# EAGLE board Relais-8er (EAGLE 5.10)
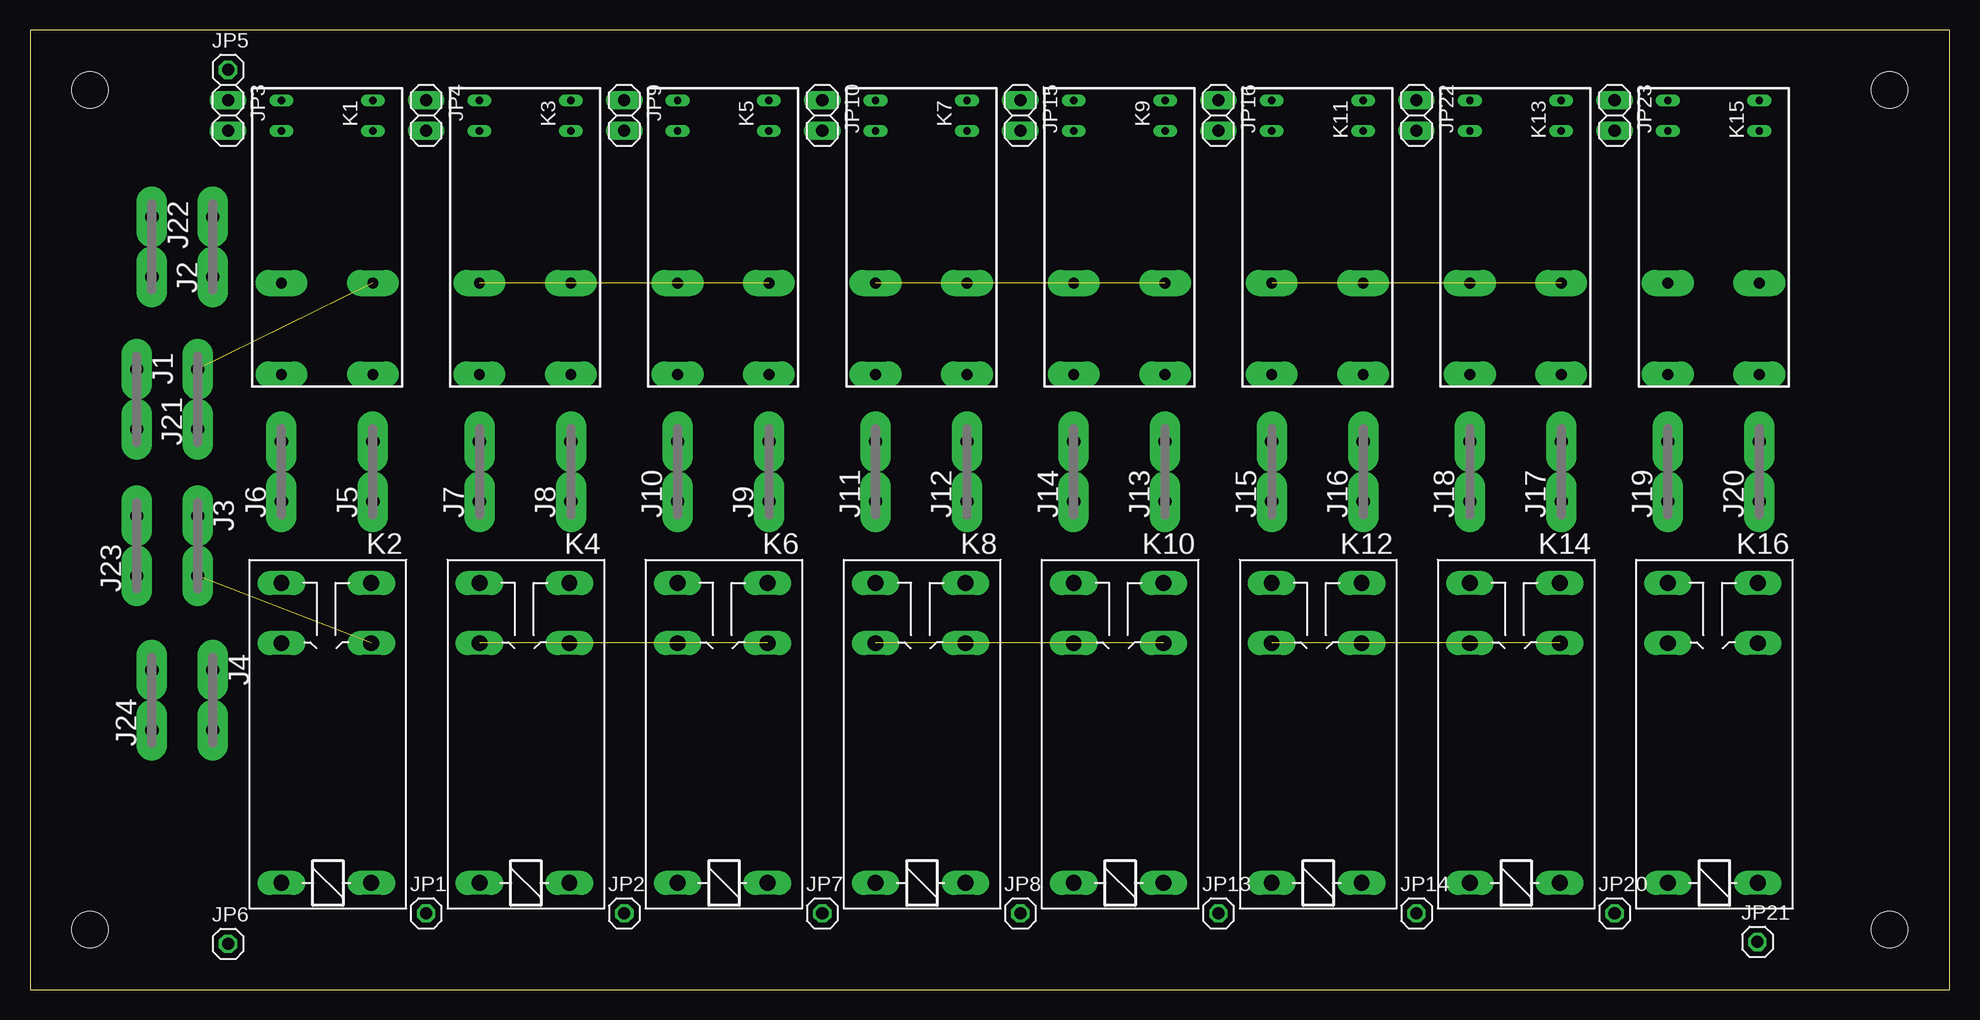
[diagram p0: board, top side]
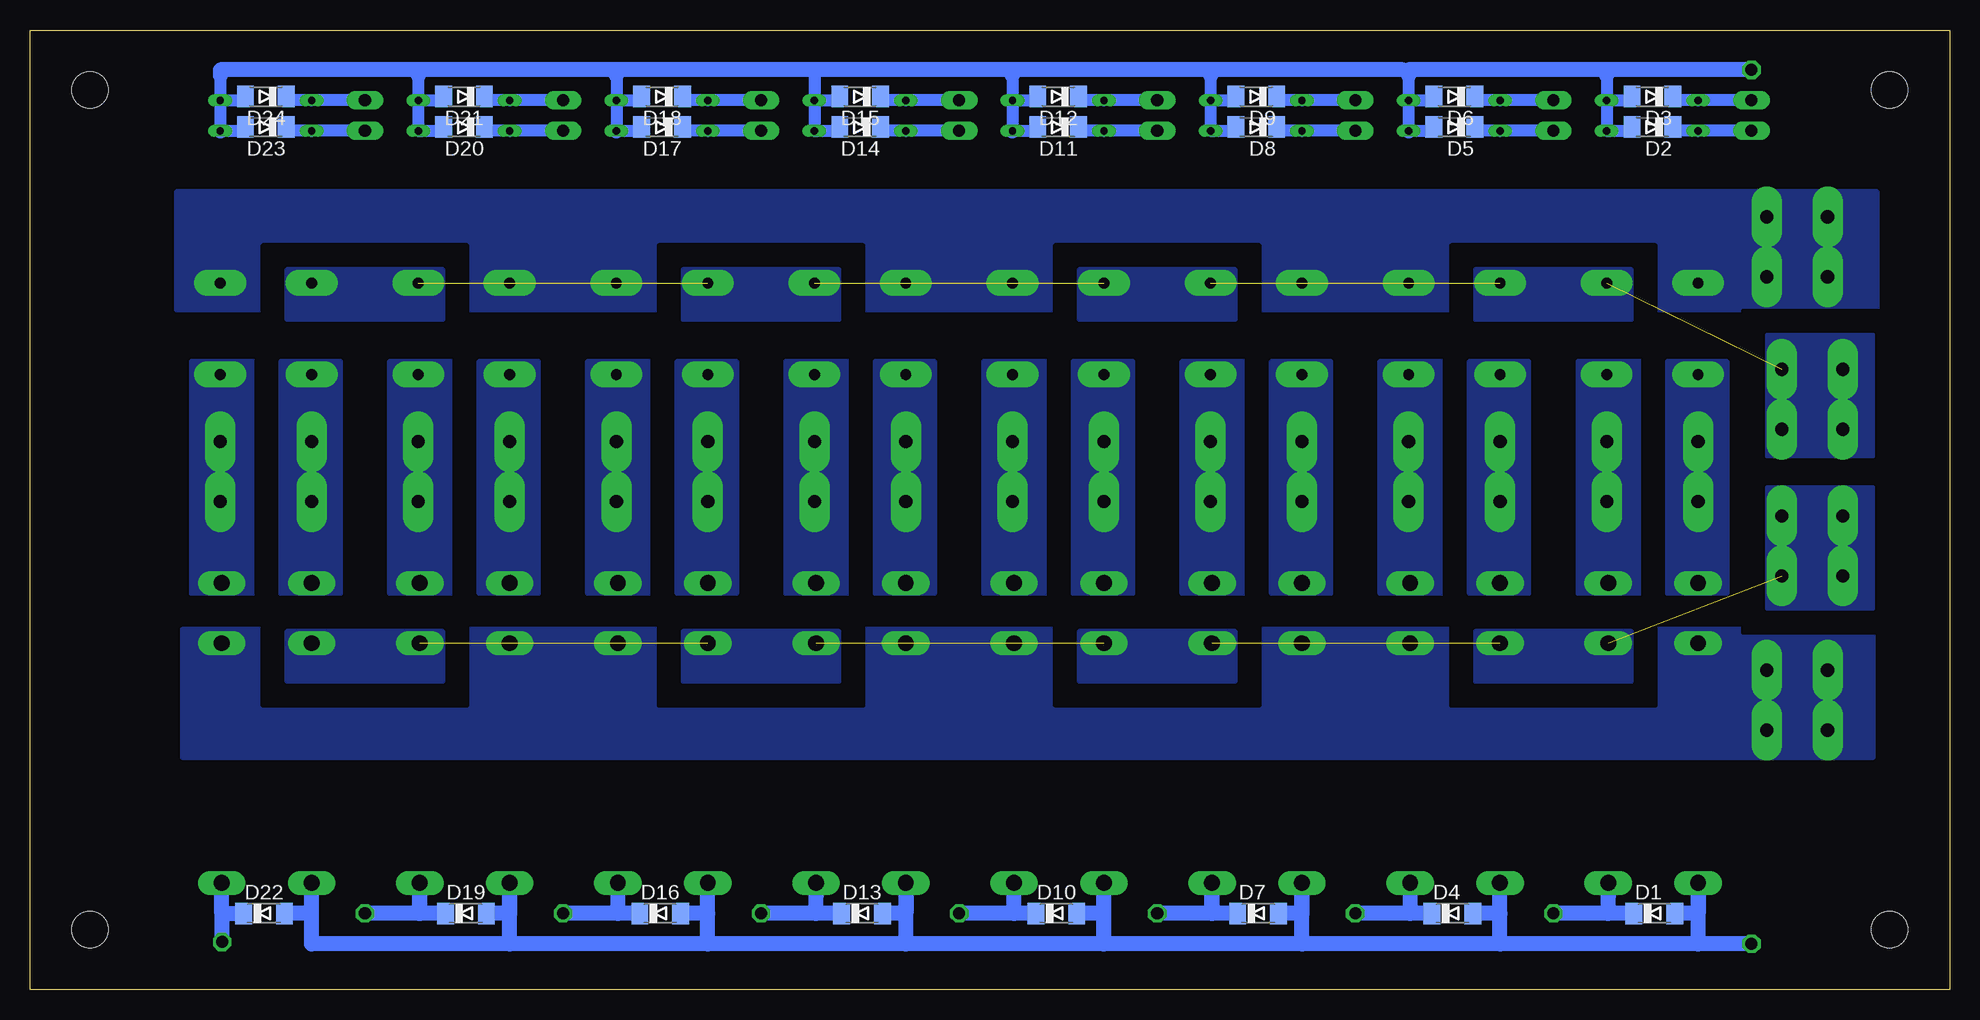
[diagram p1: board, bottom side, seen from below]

Size 160 x 80 mm. Coordinates in mm from the lower left corner, seen from the top.
Outline: 0,0 160,0 160,80 0,80 0,0
Copper layers (1+2*15+16): Top 0.035mm / dielectric 0.36mm / layer 2 0.018mm / dielectric 0.71mm / layer 15 0.018mm / dielectric 0.36mm / Bottom 0.035mm
Design rules "q-print.info": minimum track width 6mil, minimum drill 0.3mm, track to track 6mil, track to pad 6mil, pad to pad 6mil, via to via 6mil, smd to smd 6mil, copper to edge 8mil, drill to drill 10mil, minimum pad ring 8mil, minimum via ring 8mil, stop-mask expansion 4mil, vias tented up to drill 16mil, thermal gap 10mil
Net classes: 1 mains: width 4 mm, clearance 2 mm
Holes 3 mm at 5,75 5,5 155,5 155,75

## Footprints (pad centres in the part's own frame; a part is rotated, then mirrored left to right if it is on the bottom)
MINIMELF = smd 1.4 x 1.8: A 1.7,0; C -1.7,0
F061.080 = drill 1.1 pad 2.54 long: 1A -2.5,0; 1B 2.5,0
1X01 = drill 1.016 octagon: 1 0,0
1X02 = drill 1.016 long: 1 -1.27,0; 2 1.27,0
DE2A-L2 = drill 0.61 long: 1 -8.89,-3.81; 2 -6.35,-3.81; 7 -6.35,3.81; 8 -8.89,3.81 | drill 0.9 pad 2.184 long: 3 6.35,-3.81; 4 13.97,-3.81; 5 13.97,3.81; 6 6.35,3.81
G2R2A = drill 1.321 long: 1 -2.54,-3.683; 2 -2.54,3.81; P1 17.45,3.81; P2 17.45,-3.683; S1 22.454,3.81; S2 22.454,-3.683

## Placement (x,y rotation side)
D1  1N4148DO35-7  [MINIMELF]  24.61,6.35 0 bottom
D2  1N4148DO35-7  [MINIMELF]  24.77,71.91 180 bottom
D3  1N4148DO35-7  [MINIMELF]  24.76,74.45 180 bottom
D4  1N4148DO35-7  [MINIMELF]  41.43,6.35 0 bottom
D5  1N4148DO35-7  [MINIMELF]  41.27,71.91 180 bottom
D6  1N4148DO35-7  [MINIMELF]  41.27,74.45 180 bottom
D7  1N4148DO35-7  [MINIMELF]  57.63,6.35 0 bottom
D8  1N4148DO35-7  [MINIMELF]  57.78,71.91 180 bottom
D9  1N4148DO35-7  [MINIMELF]  57.78,74.45 180 bottom
D10  1N4148DO35-7  [MINIMELF]  74.45,6.35 0 bottom
D11  1N4148DO35-7  [MINIMELF]  74.29,71.91 180 bottom
D12  1N4148DO35-7  [MINIMELF]  74.3,74.45 180 bottom
D13  1N4148DO35-7  [MINIMELF]  90.65,6.35 0 bottom
D14  1N4148DO35-7  [MINIMELF]  90.81,71.91 180 bottom
D15  1N4148DO35-7  [MINIMELF]  90.8,74.45 180 bottom
D16  1N4148DO35-7  [MINIMELF]  107.47,6.35 0 bottom
D17  1N4148DO35-7  [MINIMELF]  107.31,71.91 180 bottom
D18  1N4148DO35-7  [MINIMELF]  107.31,74.45 180 bottom
D19  1N4148DO35-7  [MINIMELF]  123.67,6.35 0 bottom
D20  1N4148DO35-7  [MINIMELF]  123.83,71.91 180 bottom
D21  1N4148DO35-7  [MINIMELF]  123.82,74.45 180 bottom
D22  1N4148DO35-7  [MINIMELF]  140.49,6.35 0 bottom
D23  1N4148DO35-7  [MINIMELF]  140.33,71.91 180 bottom
D24  1N4148DO35-7  [MINIMELF]  140.34,74.45 180 bottom
J1  Netz-X1  [F061.080]  8.89,49.21 270 top
J2  Netz-X2  [F061.080]  15.24,61.91 90 top
J3  Schalter-X1  [F061.080]  13.97,36.99 270 top
J4  Schalter-X2  [F061.080]  15.24,24.13 270 top
J5  A1-X1  [F061.080]  28.57,43.18 90 top
J6  A1-X2  [F061.080]  20.95,43.18 90 top
J7  A2-X1  [F061.080]  37.47,43.18 90 top
J8  A2-X2  [F061.080]  45.09,43.18 90 top
J9  A1-X1  [F061.080]  61.59,43.18 90 top
J10  A1-X2  [F061.080]  53.98,43.18 90 top
J11  A2-X1  [F061.080]  70.48,43.18 90 top
J12  A2-X2  [F061.080]  78.11,43.18 90 top
J13  A1-X1  [F061.080]  94.61,43.18 90 top
J14  A1-X2  [F061.080]  87,43.18 90 top
J15  A2-X1  [F061.080]  103.5,43.18 90 top
J16  A2-X2  [F061.080]  111.12,43.18 90 top
J17  A1-X1  [F061.080]  127.64,43.18 90 top
J18  A1-X2  [F061.080]  120.02,43.18 90 top
J19  A2-X1  [F061.080]  136.53,43.18 90 top
J20  A2-X2  [F061.080]  144.15,43.18 90 top
J21  Netz-X1  [F061.080]  13.97,49.21 90 top
J22  Netz-X2  [F061.080]  10.16,61.91 270 top
J23  Schalter-X1  [F061.080]  8.89,36.99 90 top
J24  Schalter-X2  [F061.080]  10.16,24.13 90 top
JP1  [1X01]  33.02,6.35 0 top
JP2  [1X01]  49.53,6.35 0 top
JP3  [1X02]  16.51,72.87 270 top
JP4  [1X02]  33.02,72.87 270 top
JP5  [1X01]  16.51,76.68 0 top
JP6  [1X01]  16.51,3.81 0 top
JP7  [1X01]  66.04,6.35 0 top
JP8  [1X01]  82.55,6.35 0 top
JP9  [1X02]  49.53,72.87 270 top
JP10  [1X02]  66.04,72.87 270 top
JP13  [1X01]  99.06,6.35 0 top
JP14  [1X01]  115.57,6.35 0 top
JP15  [1X02]  82.55,72.87 270 top
JP16  [1X02]  99.06,72.87 270 top
JP20  [1X01]  132.08,6.35 0 top
JP21  [1X01]  143.99,3.97 0 top
JP22  [1X02]  115.57,72.87 270 top
JP23  [1X02]  132.08,72.87 270 top
K1  DE2A-L2  [DE2A-L2]  24.77,65.25 270 top
K2  G2R2A  [G2R2A]  24.77,11.43 90 top
K3  DE2A-L2  [DE2A-L2]  41.27,65.25 270 top
K4  G2R2A  [G2R2A]  41.27,11.43 90 top
K5  DE2A-L2  [DE2A-L2]  57.78,65.25 270 top
K6  G2R2A  [G2R2A]  57.78,11.43 90 top
K7  DE2A-L2  [DE2A-L2]  74.3,65.25 270 top
K8  G2R2A  [G2R2A]  74.3,11.43 90 top
K9  DE2A-L2  [DE2A-L2]  90.81,65.25 270 top
K10  G2R2A  [G2R2A]  90.81,11.43 90 top
K11  DE2A-L2  [DE2A-L2]  107.31,65.25 270 top
K12  G2R2A  [G2R2A]  107.31,11.43 90 top
K13  DE2A-L2  [DE2A-L2]  123.83,65.25 270 top
K14  G2R2A  [G2R2A]  123.83,11.43 90 top
K15  DE2A-L2  [DE2A-L2]  140.34,65.25 270 top
K16  G2R2A  [G2R2A]  140.34,11.43 90 top

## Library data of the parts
D1-D24 = diode
J1-J24 = con-faston
JP1-JP10 JP13-JP16 JP20-JP23 = pinhead
K1 K3 K5 K7 K9 K11 K13 K15 = 11my-mechanics
K2 K4 K6 K8 K10 K12 K14 K16 = relay

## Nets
BIGND: D2.A D3.A D5.A D6.A D8.A D9.A D11.A D12.A D14.A D15.A D17.A D18.A D20.A D21.A D23.A D24.A JP5.1 K1.7 K1.8 K3.7 K3.8 K5.7 K5.8 K7.7 K7.8 K9.7 K9.8 K11.7 K11.8 K13.7 K13.8 K15.7 K15.8
MOGND: D1.A D4.A D7.A D10.A D13.A D16.A D19.A D22.A JP6.1 K2.2 K4.2 K6.2 K8.2 K10.2 K12.2 K14.2 K16.2
N$3 [mains]: J5.1A J5.1B K1.5 K2.S2
N$4 [mains]: J6.1A J6.1B K1.4 K2.S1
N$8: D3.C JP3.1 K1.1
N$9: D2.C JP3.2 K1.2
N$11: D1.C JP1.1 K2.1
N$14 [mains]: J7.1A J7.1B K3.4 K4.S1
N$15 [mains]: J8.1A J8.1B K3.5 K4.S2
N$16 [mains]: J9.1A J9.1B K5.5 K6.S2
N$17 [mains]: J10.1A J10.1B K5.4 K6.S1
N$19: D6.C JP4.1 K3.1
N$20: D5.C JP4.2 K3.2
N$22: D4.C JP2.1 K4.1
N$24: D9.C JP9.1 K5.1
N$25: D8.C JP9.2 K5.2
N$26: D7.C JP7.1 K6.1
N$27 [mains]: J11.1A J11.1B K7.4 K8.S1
N$28 [mains]: J12.1A J12.1B K7.5 K8.S2
N$29: D12.C JP10.1 K7.1
N$30: D11.C JP10.2 K7.2
N$31: D10.C JP8.1 K8.1
N$36 [mains]: J13.1A J13.1B K9.5 K10.S2
N$38 [mains]: J14.1A J14.1B K9.4 K10.S1
N$42: D15.C JP15.1 K9.1
N$43: D14.C JP15.2 K9.2
N$44: D13.C JP13.1 K10.1
N$45 [mains]: J15.1A J15.1B K11.4 K12.S1
N$46 [mains]: J16.1A J16.1B K11.5 K12.S2
N$47: D18.C JP16.1 K11.1
N$48: D17.C JP16.2 K11.2
N$49: D16.C JP14.1 K12.1
N$53 [mains]: J17.1A J17.1B K13.5 K14.S2
N$54 [mains]: J18.1A J18.1B K13.4 K14.S1
N$58: D21.C JP22.1 K13.1
N$59: D20.C JP22.2 K13.2
N$60: D19.C JP20.1 K14.1
N$61 [mains]: J19.1A J19.1B K15.4 K16.S1
N$62 [mains]: J20.1A J20.1B K15.5 K16.S2
N$63: D24.C JP23.1 K15.1
N$64: D23.C JP23.2 K15.2
N$65: D22.C JP21.1 K16.1
NX1: J4.1A J4.1B J24.1A J24.1B K2.P1 K4.P2 K6.P1 K8.P2 K10.P1 K12.P2 K14.P1 K16.P2
NX2 [mains]: J3.1A J3.1B J23.1A J23.1B K2.P2 K4.P1 K6.P2 K8.P1 K10.P2 K12.P1 K14.P2 K16.P1
SX1: J2.1A J2.1B J22.1A J22.1B K1.3 K3.6 K5.3 K7.6 K9.3 K11.6 K13.3 K15.6
SX2 [mains]: J1.1A J1.1B J21.1A J21.1B K1.6 K3.3 K5.6 K7.3 K9.6 K11.3 K13.6 K15.3

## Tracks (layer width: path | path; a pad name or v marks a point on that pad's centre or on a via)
BIGND
  Bottom 1.016: D23.A 142.03,71.6 K15.7 K15.8 | D24.A 142.03,74.14 K15.8 | D20.A 125.53,71.6 K13.7 K13.8 | K15.8 144.15,76.2 144.15,76.68 143.99,76.68 | D21.A 125.53,74.14 K13.8 | D17.A 109.02,71.6 K11.7 K11.8 | D18.A 109.02,74.14 K11.8 | 127.64,76.2 K13.8 | D14.A 92.5,71.6 K9.7 K9.8 | D15.A 92.5,74.14 K9.8 | 111.12,76.2 K11.8 | D11.A 76,71.6 K7.7 K7.8 | D12.A 76,74.14 K7.8 | 94.61,76.68 K9.8 | D5.A 42.98,71.6 K3.7 K3.8 | D6.A 42.98,74.14 K3.8 | 78.11,76.2 K7.8 | D2.A 26.46,71.6 K1.7 K1.8 | 45.09,76.2 K3.8 | D3.A 26.46,74.14 K1.8 | 45.09,76.68 45.56,76.68 | 28.57,76.2 K1.8 | D9.A 59.48,74.14 K5.8 | K5.8 K5.7 59.48,71.6 D8.A | 61.59,76.2 K5.8 | 78.11,76.68 | 61.59,76.68
  Bottom 1.27: JP5.1 28.57,76.68 | 28.57,76.68 28.57,76.2 | 28.57,76.68 45.09,76.68 45.09,76.2 | 45.56,76.68 61.59,76.68 | 61.59,76.68 61.59,76.2 | 61.59,76.68 78.11,76.68 | 78.11,76.68 78.11,76.2 | 78.11,76.68 94.61,76.68 111.12,76.68 | 111.12,76.68 111.12,76.2 | 111.12,76.68 127.64,76.68 | 127.64,76.68 127.64,76.2 | 127.64,76.68 144.15,76.68 144.15,76.2 | K15.7 | K11.7 | K7.7 | K3.7
MOGND
  Bottom 1.27: 136.53,6.35 K16.2 | 136.53,6.35 D22.A | D19.A 120.02,6.35 K14.2 120.02,3.81 | 136.53,6.35 136.53,3.81 120.02,3.81 | 103.5,6.35 K12.2 | 103.5,6.35 D16.A | D13.A 87,6.35 K10.2 87,3.81 | 103.5,3.81 103.5,6.35 | 70.48,6.35 K8.2 | 70.48,6.35 D10.A | D7.A 53.98,6.35 K6.2 53.98,3.81 | 70.48,3.81 70.48,6.35 | D1.A 20.95,6.35 K2.2 20.95,3.81 | JP6.1 20.95,3.81 | 37.47,3.81 37.47,6.35 | 37.47,6.35 K4.2 | 37.47,6.35 D4.A | 20.95,3.81 37.47,3.81 | 37.47,3.81 53.98,3.81 | 53.98,3.81 70.48,3.81 | 70.48,3.81 87,3.81 | 87,3.81 103.5,3.81 | 103.5,3.81 120.02,3.81
N$3
  pour Bottom (isolate 2, rank 4, no thermals): 24.77,33.02 30.96,33.02 30.96,52.39 24.77,52.39
N$4
  pour Bottom (isolate 2, no thermals): 18.57,52.39 18.57,33.02 23.5,33.02 23.5,52.39
N$8
  Bottom 1.016: D3.C 23.07,74.14 K1.1 JP3.1
N$9
  Bottom 1.016: D2.C 23.07,71.6 K1.2 JP3.2
N$11
  Bottom 1.27: JP1.1 28.48,6.35 28.45,8.92 K2.1 28.45,6.35 D1.C
N$14
  pour Bottom (isolate 2, no thermals): 40.01,52.39 35.08,52.39 35.08,33.02 40.01,33.02
N$15
  pour Bottom (isolate 2, rank 4, no thermals): 41.27,33.02 47.47,33.02 47.47,52.39 41.27,52.39
N$16
  pour Bottom (isolate 2, rank 4, no thermals): 57.78,33.02 63.98,33.02 63.98,52.39 57.78,52.39
N$17
  pour Bottom (isolate 2, no thermals): 51.59,52.39 51.59,33.02 56.52,33.02 56.52,52.39
N$19
  Bottom 1.016: D6.C 39.58,74.14 K3.1 JP4.1
N$20
  Bottom 1.016: D5.C 39.58,71.6 K3.2 JP4.2
N$22
  Bottom 1.27: D4.C 44.96,6.35 | 44.96,6.35 K4.1 | 44.96,6.35 JP2.1
N$24
  Bottom 1.016: D9.C 56.09,74.14 K5.1 JP9.1
N$25
  Bottom 1.016: D8.C 56.09,71.6 K5.2 JP9.2
N$26
  Bottom 1.27: JP7.1 61.5,6.35 61.47,8.92 K6.1 61.47,6.35 D7.C
N$27
  pour Bottom (isolate 2, no thermals): 73.03,52.39 68.1,52.39 68.1,33.02 73.03,33.02
N$28
  pour Bottom (isolate 2, rank 4, no thermals): 74.3,33.02 80.49,33.02 80.49,52.39 74.3,52.39
N$29
  Bottom 1.016: D12.C 72.59,74.14 K7.1 JP10.1
N$30
  Bottom 1.016: D11.C 72.59,71.6 K7.2 JP10.2
N$31
  Bottom 1.27: D10.C 77.98,6.35 | 77.98,6.35 K8.1 | 77.98,6.35 JP8.1
N$36
  pour Bottom (isolate 2, rank 4, no thermals): 90.81,33.02 97,33.02 97,52.39 90.81,52.39
N$38
  pour Bottom (isolate 2, no thermals): 84.61,52.39 84.61,33.02 89.53,33.02 89.54,52.39
N$42
  Bottom 1.016: D15.C 89.11,74.14 K9.1 JP15.1
N$43
  Bottom 1.016: D14.C 89.11,71.6 K9.2 JP15.2
N$44
  Bottom 1.27: JP13.1 94.52,6.35 94.49,8.92 K10.1 94.49,6.35 D13.C
N$45
  pour Bottom (isolate 2, no thermals): 106.05,52.39 101.12,52.39 101.12,33.02 106.05,33.02
N$46
  pour Bottom (isolate 2, rank 4, no thermals): 107.31,33.02 113.51,33.02 113.51,52.39 107.31,52.39
N$47
  Bottom 1.016: D18.C 105.61,74.14 K11.1 JP16.1
N$48
  Bottom 1.016: D17.C 105.61,71.6 K11.2 JP16.2
N$49
  Bottom 1.27: D16.C 111,6.35 | 111,6.35 K12.1 | 111,6.35 JP14.1
N$53
  pour Bottom (isolate 2, rank 4, no thermals): 123.83,33.02 130.02,33.02 130.02,52.39 123.83,52.39
N$54
  pour Bottom (isolate 2, no thermals): 117.63,52.39 117.63,33.02 122.56,33.02 122.56,52.39
N$58
  Bottom 1.016: D21.C 122.12,74.14 K13.1 JP22.1
N$59
  Bottom 1.016: D20.C 122.12,71.6 K13.2 JP22.2
N$60
  Bottom 1.27: JP20.1 127.54,6.35 127.51,8.92 K14.1 127.51,6.35 D19.C
N$61
  pour Bottom (isolate 2, no thermals): 139.06,52.39 134.14,52.39 134.14,33.02 139.06,33.02
N$62
  pour Bottom (isolate 2, rank 4, no thermals): 140.34,33.02 146.53,33.02 146.53,52.39 140.34,52.39
N$63
  Bottom 1.016: D24.C 138.63,74.14 K15.1 JP23.1
N$64
  Bottom 1.016: D23.C 138.63,71.6 K15.2 JP23.2
N$65
  Bottom 1.27: 143.99,6.35 D22.C | K16.1 144.02,6.35 143.99,6.35 | JP21.1 143.99,6.35
NX1
  pour Bottom (isolate 2, rank 2, no thermals): 6.35,19.37 6.35,30 147.32,30 147.32,19.37
NX2  (4 unrouted)
  pour Bottom (no thermals): 26.51,29.84 39.53,29.84 39.53,25.72 26.51,25.72
  pour Bottom (no thermals): 59.53,29.84 72.55,29.84 72.55,25.72 59.53,25.72
  pour Bottom (no thermals): 92.55,29.84 105.57,29.84 105.57,25.72 92.55,25.72
  pour Bottom (no thermals): 125.57,29.84 138.59,29.84 138.59,25.72 125.57,25.72
  pour Bottom (isolate 2, no thermals): 15.24,31.75 6.35,31.75 6.35,41.91 15.24,41.91
SX1
  pour Bottom (isolate 2, rank 3, no thermals): 147.8,66.52 147.8,56.67 6.03,56.67 6.03,66.52
SX2  (4 unrouted)
  pour Bottom (no thermals): 26.51,60.01 39.53,60.01 39.53,55.88 26.51,55.88
  pour Bottom (no thermals): 59.53,60.01 72.55,60.01 72.55,55.88 59.53,55.88
  pour Bottom (no thermals): 92.55,60.01 105.57,60.01 105.57,55.88 92.55,55.88
  pour Bottom (no thermals): 125.57,60.01 138.59,60.01 138.59,55.88 125.57,55.88
  pour Bottom (isolate 2, rank 2, no thermals): 15.24,44.45 6.35,44.45 6.35,54.61 15.24,54.61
